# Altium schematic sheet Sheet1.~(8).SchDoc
size A; SheetNumber: 1; SheetTotal: 1
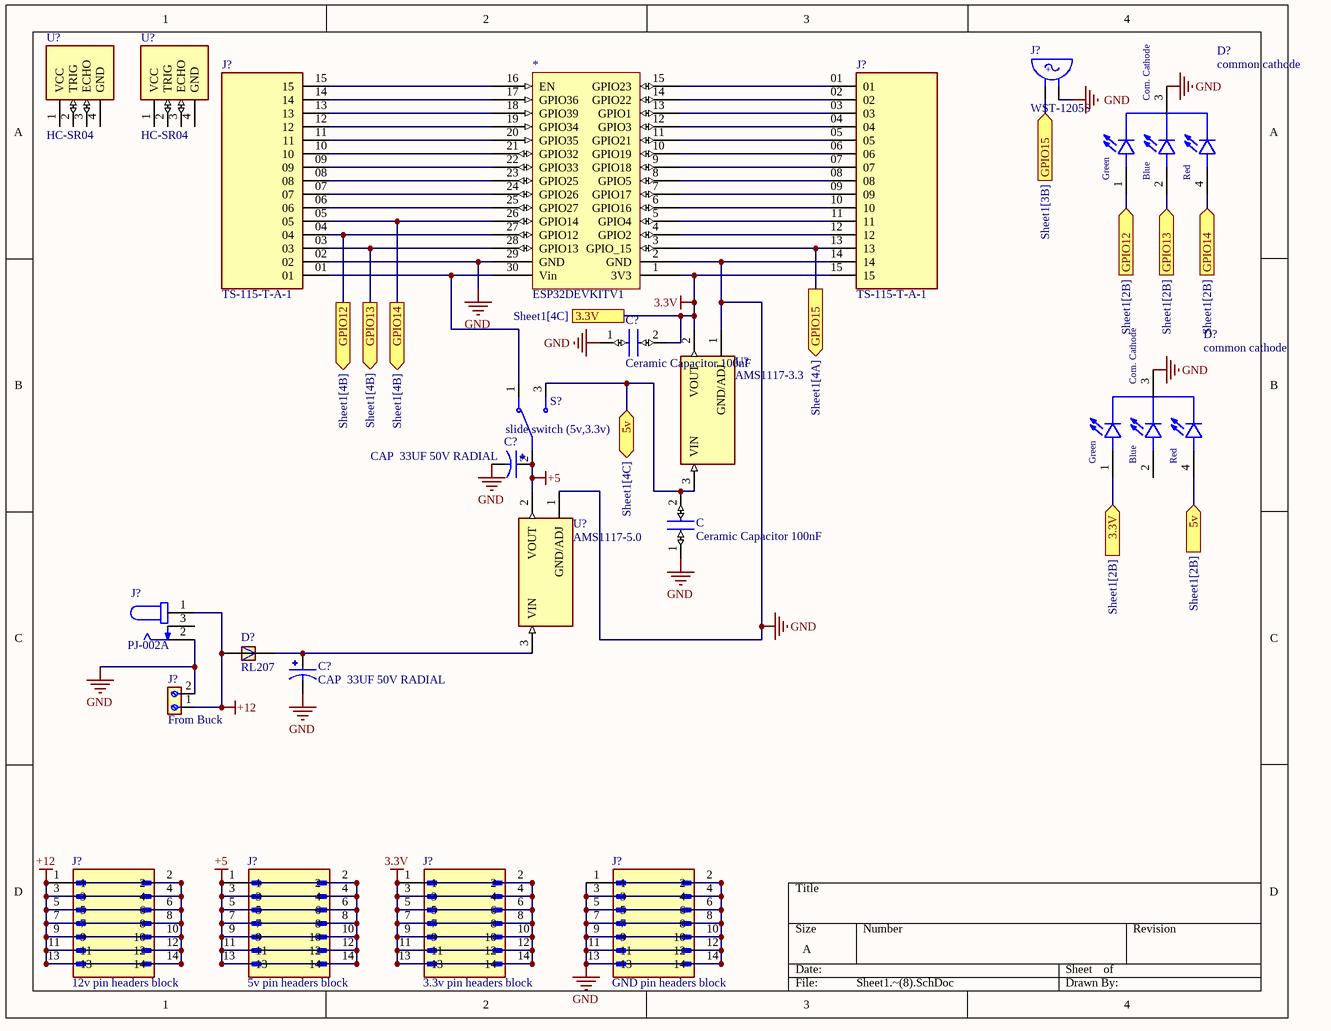
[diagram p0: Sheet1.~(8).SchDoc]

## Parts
(Parts that share a designator on the sheet are numbered #1, #2 ... from top to bottom, then left to right.)
*  ESP32DEVKITV1  [ESP32DEVKITV1]
C  Ceramic Capacitor 100nF  [C320C]
C?#1  Ceramic Capacitor 100nF  [C320C]
C?#2  CAP  33UF 50V RADIAL  [CAP  33UF 50V RADIAL]
C?#3  CAP  33UF 50V RADIAL  [CAP  33UF 50V RADIAL]
D?#1  common cathode  [LED RGB 5mm]
D?#2  common cathode  [LED RGB 5mm]
D?#3  RL207  [DIOAD1300W80L670D310]
J?#1  WST-1205S  [WST-1205S]
J?#2  TS-115-T-A-1  [SAMTEC_TS-115-T-A-1]
J?#3  TS-115-T-A-1  [SAMTEC_TS-115-T-A-1]
J?#4  PJ-002A  [CUI_PJ-002A]
J?#5  From Buck  [691213510002]
J?#6  12v pin headers block  [AMPHENOL_52601-S14-4LF]
J?#7  5v pin headers block  [AMPHENOL_52601-S14-4LF]
J?#8  3.3v pin headers block  [AMPHENOL_52601-S14-4LF]
J?#9  GND pin headers block  [AMPHENOL_52601-S14-4LF]
S?  slide switch (5v,3.3v)  [SW_EG1206]
U?#1  HC-SR04  [XCVR_HC-SR04]
U?#2  HC-SR04  [XCVR_HC-SR04]
U?#3  AMS1117-3.3  [SOT229P700X180-4N]
U?#4  AMS1117-5.0  [SOT229P700X180-4N]

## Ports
3.3V (in, see Sheet1[2B]), 3.3V (see Sheet1[4C]), 5v (bidir, see Sheet1[4C]), 5v (in, see Sheet1[2B]), GPIO12 (in, see Sheet1[2B]), GPIO12 (out, see Sheet1[4B]), GPIO13 (in, see Sheet1[2B]), GPIO13 (out, see Sheet1[4B]), GPIO14 (in, see Sheet1[2B]), GPIO14 (out, see Sheet1[4B]), GPIO15 (in, see Sheet1[3B]), GPIO15 (out, see Sheet1[4A])

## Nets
3.3V: *.1(3V3) C?#1.2 D?#2.1(Green) J?#3.15 J?#8.1 J?#8.2 J?#8.3 J?#8.4 J?#8.5 J?#8.6 J?#8.7 J?#8.8 J?#8.9 J?#8.10 J?#8.11 J?#8.12 J?#8.13 J?#8.14 U?#3.2(VOUT) ; port 3.3V
 GND: *.2(GND) *.29(GND) C.1 C?#1.1 C?#2.N C?#3.N D?#1.3(Com._Cathode) D?#2.3(Com._Cathode) J?#1.NEG J?#2.02 J?#3.14 J?#4.2 J?#5.2 J?#9.1 J?#9.2 J?#9.3 J?#9.4 J?#9.5 J?#9.6 J?#9.7 J?#9.8 J?#9.9 J?#9.10 J?#9.11 J?#9.12 J?#9.13 J?#9.14 U?#3.1(GND/ADJ) U?#4.1(GND/ADJ)  [also labelled GND]
+5: C?#2.P J?#7.1 J?#7.2 J?#7.3 J?#7.4 J?#7.5 J?#7.6 J?#7.7 J?#7.8 J?#7.9 J?#7.10 J?#7.11 J?#7.12 J?#7.13 J?#7.14 S?.2 U?#4.2(VOUT)
+12: D?#3.A J?#4.1 J?#5.1 J?#6.1 J?#6.2 J?#6.3 J?#6.4 J?#6.5 J?#6.6 J?#6.7 J?#6.8 J?#6.9 J?#6.10 J?#6.11 J?#6.12 J?#6.13 J?#6.14
5v: C.2 D?#2.4(Red) S?.3 U?#3.3(VIN) ; port 5v
GPIO12: *.27(GPIO12) D?#1.1(Green) J?#2.04 ; port GPIO12
GPIO13: *.28(GPIO13) D?#1.2(BLUE) J?#2.03 ; port GPIO13
GPIO14: *.26(GPIO14) D?#1.4(Red) J?#2.05 ; port GPIO14
GPIO15: *.3(GPIO_15) J?#1.POS J?#3.13 ; port GPIO15
Net*_4: *.4(GPIO2) J?#3.12
Net*_5: *.5(GPIO4) J?#3.11
Net*_6: *.6(GPIO16) J?#3.10
Net*_7: *.7(GPIO17) J?#3.09
Net*_8: *.8(GPIO5) J?#3.08
Net*_9: *.9(GPIO18) J?#3.07
Net*_10: *.10(GPIO19) J?#3.06
Net*_11: *.11(GPIO21) J?#3.05
Net*_12: *.12(GPIO3) J?#3.04
Net*_13: *.13(GPIO1) J?#3.03
Net*_14: *.14(GPIO22) J?#3.02
Net*_15: *.15(GPIO23) J?#3.01
Net*_16: *.16(EN) J?#2.15
Net*_17: *.17(GPIO36) J?#2.14
Net*_18: *.18(GPIO39) J?#2.13
Net*_19: *.19(GPIO34) J?#2.12
Net*_20: *.20(GPIO35) J?#2.11
Net*_21: *.21(GPIO32) J?#2.10
Net*_22: *.22(GPIO33) J?#2.09
Net*_23: *.23(GPIO25) J?#2.08
Net*_24: *.24(GPIO26) J?#2.07
Net*_25: *.25(GPIO27) J?#2.06
Net*_30: *.30(Vin) J?#2.01 S?.1
NetC?#3_P: C?#3.P D?#3.C U?#4.3(VIN)

Not connected (* = marked no-connect by the designer): D?#2 2(BLUE); J?#4 3; U?#1 1(VCC) 2(TRIG) 3(ECHO) 4(GND); U?#2 1(VCC) 2(TRIG) 3(ECHO) 4(GND)

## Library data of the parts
C C?#1 = Ceramic Capacitor 100nF: 0.1ÂµF Â±20% 50V Ceramic Capacitor Z5U Radial; MF: KEMET; MP: C320C104M5U5TA
C?#2 C?#3 = CAP  33UF 50V RADIAL: NHG-A; MF: {'manufacturer': u'Panasonic'}; MP: ECA1HHG330I
D?#1 D?#2 = LED RGB 5mm: MF: {'manufacturer': u'Kingbright'}; MP: WP154A4SUREQBFZGC
D?#3 = RL207: Semiconductors and Actives, Power Diodes, Discretes (diodes, transistors, thyristors ...), Diodes; MF: {'manufacturer': u'Diodes Inc.'}
J?#1 = WST-1205S: BUZZER 2.3KHZ 4-6VDC; MF: {'manufacturer': u'Soberton Inc.'}
J?#2 J?#3 = TS-115-T-A-1: MF: {'manufacturer': u'Samtec'}
J?#4 = PJ-002A: 2.0 mm Center Pin, 2.5 A, Right Angle, Through Hole, Dc Power Jack Connector; MF: {'manufacturer': u'CUI Devices'}
J?#5 = Terminal Block: 2 Position Wire to Board Terminal Block Horizontal with Board 0.200 (5.08mm) Through Hole; MF: Wurth Electronics
J?#6-J?#9 = 52601-S14-4LF: MF: {'manufacturer': u'Amphenol ICC (FCI)'}
S? = EG1206: MF: {'manufacturer': u'E-Switch'}
U?#1 U?#2 = HC-SR04: Ultrasonic Sensor Module; MF: {'manufacturer': u'UNIVERSAL-SOLDER Electronics Ltd'}
U?#3 = AMS1117-3.3: MF: {'manufacturer': u'Advanced Monolithic Systems'}
U?#4 = AMS1117-5.0: MF: {'manufacturer': u'Advanced Monolithic Systems'}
